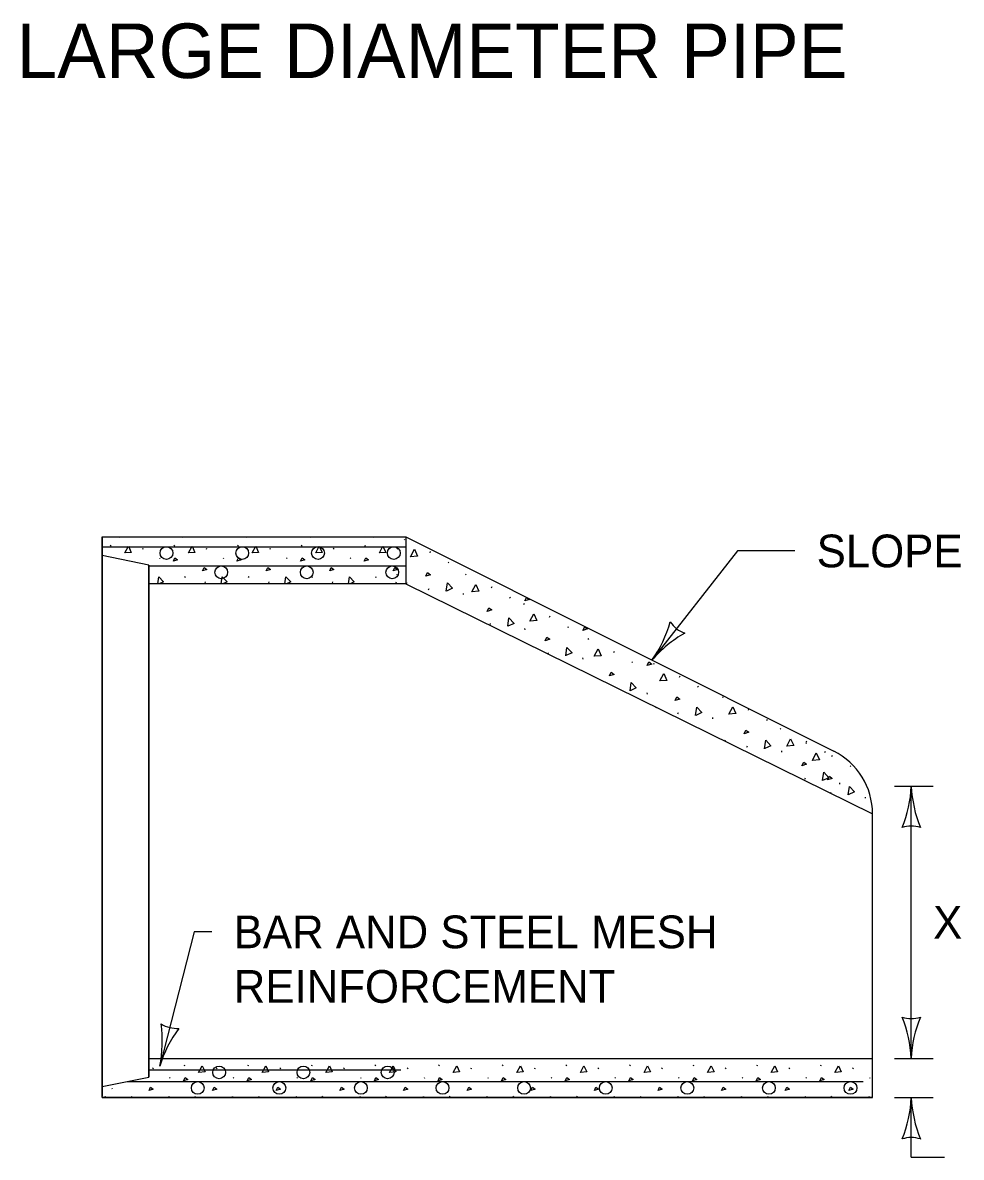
# Model space of a CAD drawing. Extents: x 49991.4 to 50021, y 49987.6 to 50011.4.
# Drawn here: x 50002.773 to 50004.494, y 49990.143 to 49992.222 of the extents above; entities that cross this region are included whole.
import ezdxf

# ---------------------------------------------------------------- set-up
doc = ezdxf.new("R2010")
doc.units = 0
for name, color, linetype in [('Level 1', 7, 'Continuous'), ('Level 2', 7, 'Continuous'), ('Level 3', 7, 'Continuous')]:
    doc.layers.add(name, color=color, linetype=linetype)

msp = doc.modelspace()

# ---------------------------------------------------------------- linework, layer by layer
at = {"layer": 'Level 1'}
for p, q in [((50002.9188, 49991.2797), (50003.4753, 49991.2797)), ((50002.9188, 49990.2549), (50002.9188, 49991.2797)), ((50002.9188, 49991.2797), (50002.9188, 49990.2723)), ((50002.9188, 49991.2797), (50003.4753, 49991.2797)), ((50002.9188, 49991.2797), (50002.9188, 49990.2549)), ((50002.9188, 49990.2549), (50002.9188, 49991.2797)), ((50002.9188, 49990.2549), (50002.9188, 49991.2797)), ((50002.9188, 49990.2549), (50002.9188, 49991.2797)), ((50002.9493, 49991.2797), (50002.9495, 49991.2793)), ((50002.9499, 49991.2797), (50002.9505, 49991.2788)), ((50003.0659, 49991.2797), (50003.0662, 49991.2793)), ((50003.0666, 49991.2797), (50003.0672, 49991.2788)), ((50003.1826, 49991.2797), (50003.1829, 49991.2793)), ((50003.1833, 49991.2797), (50003.1839, 49991.2788)), ((50003.2993, 49991.2797), (50003.2996, 49991.2793)), ((50003.3, 49991.2797), (50003.3006, 49991.2788)), ((50003.416, 49991.2797), (50003.4163, 49991.2793)), ((50003.4167, 49991.2797), (50003.4173, 49991.2788)), ((50003.4723, 49991.276), (50003.4734, 49991.2744)), ((50003.4753, 49991.2797), (50004.2605, 49990.8871)), ((50003.4753, 49991.2797), (50003.4753, 49991.1941)), ((50003.4753, 49991.2797), (50003.4753, 49991.1941)), ((50002.9342, 49991.2627), (50002.9352, 49991.2649)), ((50002.9931, 49991.2571), (50002.9941, 49991.2593)), ((50003.0509, 49991.2627), (50003.0518, 49991.2649)), ((50003.1098, 49991.2571), (50003.1108, 49991.2593)), ((50003.1676, 49991.2627), (50003.1685, 49991.2649)), ((50003.2265, 49991.2571), (50003.2275, 49991.2593)), ((50003.2843, 49991.2627), (50003.2852, 49991.2649)), ((50003.3432, 49991.2571), (50003.3442, 49991.2593)), ((50003.4009, 49991.2627), (50003.4019, 49991.2649)), ((50003.4599, 49991.2571), (50003.4609, 49991.2593)), ((50003.52, 49991.2507), (50003.5211, 49991.2531)), ((50003.0045, 49991.2283), (50002.9188, 49991.2455)), ((50003.0045, 49991.2283), (50002.9188, 49991.2455)), ((50002.9188, 49990.2523), (50002.9188, 49991.2455)), ((50003.0236, 49991.2416), (50003.0246, 49991.2401)), ((50003.1403, 49991.2416), (50003.1413, 49991.2401)), ((50003.257, 49991.2416), (50003.2579, 49991.2401)), ((50003.3737, 49991.2416), (50003.3746, 49991.2401)), ((50003.5533, 49991.2337), (50003.5544, 49991.2321)), ((50003.0045, 49990.2895), (50003.0045, 49991.2283)), ((50003.0045, 49991.2283), (50003.0045, 49990.2895)), ((50003.0045, 49991.2283), (50003.0045, 49990.2895)), ((50003.0045, 49991.2283), (50003.0045, 49990.2895)), ((50003.4582, 49991.2115), (50003.4589, 49991.2104)), ((50003.5849, 49991.2117), (50003.586, 49991.2101)), ((50003.4753, 49991.1941), (50003.0045, 49991.1941)), ((50003.4753, 49991.1941), (50003.0045, 49991.1941)), ((50003.0704, 49991.2053), (50003.0713, 49991.2074)), ((50003.1074, 49991.1953), (50003.1084, 49991.1975)), ((50003.1871, 49991.2053), (50003.188, 49991.2074)), ((50003.2241, 49991.1953), (50003.2251, 49991.1975)), ((50003.3037, 49991.2053), (50003.3047, 49991.2074)), ((50003.3408, 49991.1953), (50003.3417, 49991.1975)), ((50003.4204, 49991.2053), (50003.4214, 49991.2074)), ((50003.4575, 49991.1953), (50003.4584, 49991.1975)), ((50003.4753, 49991.1941), (50004.3315, 49990.7722)), ((50003.4769, 49991.194), (50003.4779, 49991.1964)), ((50003.6326, 49991.1864), (50003.6337, 49991.1888)), ((50003.5174, 49991.1831), (50003.5184, 49991.1855)), ((50003.5807, 49991.1764), (50003.581, 49991.174)), ((50003.6659, 49991.1694), (50003.667, 49991.1678)), ((50003.6914, 49991.1578), (50003.6925, 49991.1562)), ((50003.7391, 49991.1325), (50003.7402, 49991.1349)), ((50003.63, 49991.1188), (50003.631, 49991.1212)), ((50003.6933, 49991.1121), (50003.6936, 49991.1097)), ((50003.7724, 49991.1155), (50003.7735, 49991.1139)), ((50003.8092, 49991.0934), (50003.8103, 49991.0918)), ((50003.7365, 49991.0649), (50003.7375, 49991.0673)), ((50003.8569, 49991.0681), (50003.858, 49991.0705)), ((50003.7998, 49991.0582), (50003.8001, 49991.0558)), ((50003.8902, 49991.0511), (50003.8913, 49991.0495)), ((50003.9296, 49991.0483), (50003.9307, 49991.0467)), ((50003.9773, 49991.023), (50003.9784, 49991.0254)), ((50004.0106, 49991.006), (50004.0117, 49991.0044)), ((50003.9176, 49990.9938), (50003.9179, 49990.9914)), ((50004.0561, 49990.9874), (50004.0572, 49990.9858)), ((50003.9342, 49990.9663), (50003.9352, 49990.9687)), ((50004.1038, 49990.9621), (50004.1049, 49990.9645)), ((50003.9747, 49990.9554), (50003.9757, 49990.9578)), ((50004.038, 49990.9487), (50004.0383, 49990.9463)), ((50004.1371, 49990.9451), (50004.1382, 49990.9435)), ((50004.1623, 49990.9288), (50004.1634, 49990.9272)), ((50004.0607, 49990.9054), (50004.0617, 49990.9078)), ((50004.1012, 49990.8945), (50004.1022, 49990.8969)), ((50004.2094, 49990.9027), (50004.2105, 49990.9011)), ((50004.21, 49990.9035), (50004.2111, 49990.9059)), ((50004.1645, 49990.8878), (50004.1648, 49990.8854)), ((50004.2433, 49990.8865), (50004.2444, 49990.8849)), ((50004.2571, 49990.8774), (50004.2582, 49990.8798)), ((50004.2904, 49990.8604), (50004.2915, 49990.8588)), ((50004.2074, 49990.8359), (50004.2084, 49990.8383)), ((50004.2707, 49990.8292), (50004.271, 49990.8268)), ((50004.2545, 49990.8098), (50004.2555, 49990.8122)), ((50004.3178, 49990.8031), (50004.3181, 49990.8007)), ((50004.3315, 49990.2523), (50004.3315, 49990.7722)), ((50004.3315, 49990.2523), (50004.3315, 49990.7722)), ((50003.0045, 49990.3237), (50004.3315, 49990.3237)), ((50003.0045, 49990.2895), (50003.0045, 49990.3237)), ((50003.0045, 49990.3237), (50004.3315, 49990.3237)), ((50003.0118, 49990.3047), (50003.0128, 49990.3069)), ((50003.0696, 49990.3103), (50003.0705, 49990.3125)), ((50003.1285, 49990.3047), (50003.1295, 49990.3069)), ((50003.1862, 49990.3103), (50003.1872, 49990.3125)), ((50003.2452, 49990.3047), (50003.2462, 49990.3069)), ((50003.3029, 49990.3103), (50003.3039, 49990.3125)), ((50003.3619, 49990.3047), (50003.3629, 49990.3069)), ((50003.4196, 49990.3103), (50003.4206, 49990.3125)), ((50003.4786, 49990.3047), (50003.4796, 49990.3069)), ((50003.5363, 49990.3103), (50003.5373, 49990.3125)), ((50003.5953, 49990.3047), (50003.5962, 49990.3069)), ((50003.653, 49990.3103), (50003.654, 49990.3125)), ((50003.712, 49990.3047), (50003.7129, 49990.3069)), ((50003.7697, 49990.3103), (50003.7707, 49990.3125)), ((50003.8286, 49990.3047), (50003.8296, 49990.3069)), ((50003.8864, 49990.3103), (50003.8874, 49990.3125)), ((50003.9453, 49990.3047), (50003.9463, 49990.3069)), ((50004.0031, 49990.3103), (50004.004, 49990.3125)), ((50004.062, 49990.3047), (50004.063, 49990.3069)), ((50004.1198, 49990.3103), (50004.1207, 49990.3125)), ((50004.1787, 49990.3047), (50004.1797, 49990.3069)), ((50004.2365, 49990.3103), (50004.2374, 49990.3125)), ((50004.2954, 49990.3047), (50004.2964, 49990.3069)), ((50002.9188, 49990.2723), (50003.0045, 49990.2895)), ((50003.0423, 49990.2892), (50003.0432, 49990.2877)), ((50003.159, 49990.2892), (50003.1599, 49990.2877)), ((50003.2757, 49990.2892), (50003.2766, 49990.2877)), ((50003.3923, 49990.2892), (50003.3933, 49990.2877)), ((50003.509, 49990.2892), (50003.51, 49990.2877)), ((50003.6257, 49990.2892), (50003.6267, 49990.2877)), ((50003.7424, 49990.2892), (50003.7434, 49990.2877)), ((50003.8591, 49990.2892), (50003.8601, 49990.2877)), ((50003.9758, 49990.2892), (50003.9768, 49990.2877)), ((50004.0925, 49990.2892), (50004.0935, 49990.2877)), ((50004.2092, 49990.2892), (50004.2101, 49990.2877)), ((50004.3259, 49990.2892), (50004.3268, 49990.2877)), ((50004.3315, 49990.2523), (50002.9188, 49990.2523)), ((50004.3315, 49990.2523), (50002.9188, 49990.2523)), ((50002.9188, 49990.2523), (50004.3315, 49990.2523)), ((50002.9361, 49990.2696), (50002.9368, 49990.2685)), ((50002.9724, 49990.2529), (50002.9733, 49990.255)), ((50003.089, 49990.2529), (50003.09, 49990.255)), ((50003.2057, 49990.2529), (50003.2067, 49990.255)), ((50003.3224, 49990.2529), (50003.3234, 49990.255)), ((50003.4391, 49990.2529), (50003.4401, 49990.255)), ((50003.5558, 49990.2529), (50003.5568, 49990.255)), ((50003.6725, 49990.2529), (50003.6735, 49990.255)), ((50003.7892, 49990.2529), (50003.7902, 49990.255)), ((50003.9059, 49990.2529), (50003.9068, 49990.255)), ((50004.0226, 49990.2529), (50004.0235, 49990.255)), ((50004.1393, 49990.2529), (50004.1402, 49990.255)), ((50004.2559, 49990.2529), (50004.2569, 49990.255))]:
    msp.add_line(p, q, dxfattribs=at)
for points in [[(50002.9195, 49991.2619), (50003.4753, 49991.2619)], [(50002.9603, 49991.2506), (50002.9668, 49991.263), (50002.9719, 49991.2515), (50002.9605, 49991.2506)], [(50003.0769, 49991.2506), (50003.0835, 49991.263), (50003.0886, 49991.2515), (50003.0772, 49991.2506)], [(50003.1936, 49991.2506), (50003.2002, 49991.263), (50003.2053, 49991.2515), (50003.1939, 49991.2506)], [(50003.3103, 49991.2506), (50003.3169, 49991.263), (50003.322, 49991.2515), (50003.3106, 49991.2506)], [(50003.427, 49991.2506), (50003.4336, 49991.263), (50003.4387, 49991.2515), (50003.4273, 49991.2506)], [(50003.4841, 49991.2436), (50003.4913, 49991.2571), (50003.4969, 49991.2446), (50003.4843, 49991.2436)], [(50003.0492, 49991.2352), (50003.0521, 49991.2413), (50003.057, 49991.2377), (50003.0492, 49991.2352)], [(50003.1659, 49991.2352), (50003.1688, 49991.2413), (50003.1737, 49991.2377), (50003.1659, 49991.2352)], [(50003.2825, 49991.2352), (50003.2855, 49991.2413), (50003.2903, 49991.2377), (50003.2825, 49991.2352)], [(50003.3992, 49991.2352), (50003.4022, 49991.2413), (50003.407, 49991.2377), (50003.3992, 49991.2352)], [(50003.0048, 49991.2267), (50003.4753, 49991.2267)], [(50003.1026, 49991.2178), (50003.1055, 49991.2239), (50003.1104, 49991.2202), (50003.1026, 49991.2178)], [(50003.2193, 49991.2178), (50003.2222, 49991.2239), (50003.2271, 49991.2202), (50003.2193, 49991.2178)], [(50003.3359, 49991.2178), (50003.3389, 49991.2239), (50003.3437, 49991.2202), (50003.3359, 49991.2178)], [(50003.4526, 49991.2178), (50003.4556, 49991.2239), (50003.4604, 49991.2202), (50003.4526, 49991.2178)], [(50003.5121, 49991.2077), (50003.5153, 49991.2144), (50003.5206, 49991.2104), (50003.5121, 49991.2077)], [(50003.0205, 49991.1941), (50003.0223, 49991.2067), (50003.031, 49991.1977), (50003.0234, 49991.1941)], [(50003.1372, 49991.1941), (50003.139, 49991.2067), (50003.1477, 49991.1977), (50003.1401, 49991.1941)], [(50003.2539, 49991.1941), (50003.2556, 49991.2067), (50003.2644, 49991.1977), (50003.2567, 49991.1941)], [(50003.3706, 49991.1941), (50003.3723, 49991.2067), (50003.3811, 49991.1977), (50003.3734, 49991.1941)], [(50003.5498, 49991.1803), (50003.5519, 49991.1956), (50003.5614, 49991.1857), (50003.55, 49991.1804)], [(50003.5967, 49991.1793), (50003.6039, 49991.1928), (50003.6095, 49991.1803), (50003.5969, 49991.1793)], [(50003.6939, 49991.1625), (50003.6971, 49991.1691), (50003.7024, 49991.1651), (50003.6939, 49991.1625)], [(50003.6247, 49991.1434), (50003.6279, 49991.1501), (50003.6332, 49991.1461), (50003.6247, 49991.1434)], [(50003.6624, 49991.116), (50003.6645, 49991.1313), (50003.674, 49991.1214), (50003.6626, 49991.1161)], [(50003.7032, 49991.1254), (50003.7104, 49991.1389), (50003.716, 49991.1264), (50003.7034, 49991.1254)], [(50003.8004, 49991.1086), (50003.8036, 49991.1152), (50003.8089, 49991.1112), (50003.8004, 49991.1086)], [(50003.7312, 49991.0895), (50003.7344, 49991.0962), (50003.7397, 49991.0922), (50003.7312, 49991.0895)], [(50003.7689, 49991.0621), (50003.771, 49991.0774), (50003.7805, 49991.0675), (50003.7691, 49991.0622)], [(50003.821, 49991.061), (50003.8282, 49991.0745), (50003.8338, 49991.062), (50003.8212, 49991.061)], [(50003.9182, 49991.0442), (50003.9214, 49991.0508), (50003.9267, 49991.0468), (50003.9182, 49991.0442)], [(50003.849, 49991.0251), (50003.8522, 49991.0318), (50003.8575, 49991.0278), (50003.849, 49991.0251)], [(50003.9414, 49991.0159), (50003.9486, 49991.0294), (50003.9542, 49991.0169), (50003.9416, 49991.0159)], [(50003.8867, 49990.9977), (50003.8888, 49991.013), (50003.8983, 49991.0031), (50003.8869, 49990.9978)], [(50003.9694, 49990.98), (50003.9726, 49990.9867), (50003.9779, 49990.9827), (50003.9694, 49990.98)], [(50004.0071, 49990.9526), (50004.0092, 49990.9679), (50004.0187, 49990.958), (50004.0073, 49990.9527)], [(50004.0679, 49990.955), (50004.0751, 49990.9685), (50004.0807, 49990.956), (50004.0681, 49990.955)], [(50004.0959, 49990.9191), (50004.0991, 49990.9258), (50004.1044, 49990.9218), (50004.0959, 49990.9191)], [(50004.1336, 49990.8917), (50004.1357, 49990.907), (50004.1452, 49990.8971), (50004.1338, 49990.8918)], [(50004.1741, 49990.8964), (50004.1813, 49990.9099), (50004.1869, 49990.8974), (50004.1743, 49990.8964)], [(50004.2212, 49990.8703), (50004.2284, 49990.8838), (50004.234, 49990.8713), (50004.2214, 49990.8703)], [(50004.2021, 49990.8605), (50004.2053, 49990.8672), (50004.2106, 49990.8632), (50004.2021, 49990.8605)], [(50004.2398, 49990.8331), (50004.2419, 49990.8484), (50004.2514, 49990.8385), (50004.24, 49990.8332)], [(50004.2492, 49990.8344), (50004.2524, 49990.8411), (50004.2577, 49990.8371), (50004.2492, 49990.8344)], [(50004.2869, 49990.807), (50004.289, 49990.8223), (50004.2985, 49990.8124), (50004.2871, 49990.8071)], [(50003.0045, 49990.3031), (50003.4665, 49990.3031)], [(50003.0956, 49990.2982), (50003.1022, 49990.3106), (50003.1073, 49990.2991), (50003.0959, 49990.2982)], [(50003.2123, 49990.2982), (50003.2189, 49990.3106), (50003.224, 49990.2991), (50003.2126, 49990.2982)], [(50003.329, 49990.2982), (50003.3356, 49990.3106), (50003.3407, 49990.2991), (50003.3292, 49990.2982)], [(50003.4457, 49990.2982), (50003.4523, 49990.3106), (50003.4574, 49990.2991), (50003.4459, 49990.2982)], [(50003.5624, 49990.2982), (50003.569, 49990.3106), (50003.5741, 49990.2991), (50003.5626, 49990.2982)], [(50003.6791, 49990.2982), (50003.6857, 49990.3106), (50003.6908, 49990.2991), (50003.6793, 49990.2982)], [(50003.7958, 49990.2982), (50003.8023, 49990.3106), (50003.8075, 49990.2991), (50003.796, 49990.2982)], [(50003.9125, 49990.2982), (50003.919, 49990.3106), (50003.9241, 49990.2991), (50003.9127, 49990.2982)], [(50004.0291, 49990.2982), (50004.0357, 49990.3106), (50004.0408, 49990.2991), (50004.0294, 49990.2982)], [(50004.1458, 49990.2982), (50004.1524, 49990.3106), (50004.1575, 49990.2991), (50004.1461, 49990.2982)], [(50004.2625, 49990.2982), (50004.2691, 49990.3106), (50004.2742, 49990.2991), (50004.2628, 49990.2982)], [(50002.9651, 49990.2816), (50004.3146, 49990.2816)], [(50003.0679, 49990.2828), (50003.0708, 49990.2889), (50003.0756, 49990.2853), (50003.0679, 49990.2828)], [(50003.1845, 49990.2828), (50003.1875, 49990.2889), (50003.1923, 49990.2853), (50003.1845, 49990.2828)], [(50003.3012, 49990.2828), (50003.3042, 49990.2889), (50003.309, 49990.2853), (50003.3012, 49990.2828)], [(50003.4179, 49990.2828), (50003.4208, 49990.2889), (50003.4257, 49990.2853), (50003.4179, 49990.2828)], [(50003.5346, 49990.2828), (50003.5375, 49990.2889), (50003.5424, 49990.2853), (50003.5346, 49990.2828)], [(50003.6513, 49990.2828), (50003.6542, 49990.2889), (50003.6591, 49990.2853), (50003.6513, 49990.2828)], [(50003.768, 49990.2828), (50003.7709, 49990.2889), (50003.7758, 49990.2853), (50003.768, 49990.2828)], [(50003.8847, 49990.2828), (50003.8876, 49990.2889), (50003.8925, 49990.2853), (50003.8847, 49990.2828)], [(50004.0014, 49990.2828), (50004.0043, 49990.2889), (50004.0092, 49990.2853), (50004.0014, 49990.2828)], [(50004.1181, 49990.2828), (50004.121, 49990.2889), (50004.1259, 49990.2853), (50004.1181, 49990.2828)], [(50004.2347, 49990.2828), (50004.2377, 49990.2889), (50004.2425, 49990.2853), (50004.2347, 49990.2828)], [(50002.924, 49990.2523), (50002.9243, 49990.2543), (50002.9262, 49990.2523)], [(50003.0046, 49990.2654), (50003.0075, 49990.2715), (50003.0124, 49990.2678), (50003.0046, 49990.2654)], [(50003.0407, 49990.2523), (50003.041, 49990.2543), (50003.0429, 49990.2523)], [(50003.1213, 49990.2654), (50003.1242, 49990.2715), (50003.129, 49990.2678), (50003.1213, 49990.2654)], [(50003.1573, 49990.2523), (50003.1576, 49990.2543), (50003.1596, 49990.2523)], [(50003.2379, 49990.2654), (50003.2409, 49990.2715), (50003.2457, 49990.2678), (50003.2379, 49990.2654)], [(50003.274, 49990.2523), (50003.2743, 49990.2543), (50003.2763, 49990.2523)], [(50003.3546, 49990.2654), (50003.3576, 49990.2715), (50003.3624, 49990.2678), (50003.3546, 49990.2654)], [(50003.3907, 49990.2523), (50003.391, 49990.2543), (50003.3929, 49990.2523)], [(50003.4713, 49990.2654), (50003.4742, 49990.2715), (50003.4791, 49990.2678), (50003.4713, 49990.2654)], [(50003.5074, 49990.2523), (50003.5077, 49990.2543), (50003.5096, 49990.2523)], [(50003.588, 49990.2654), (50003.5909, 49990.2715), (50003.5958, 49990.2678), (50003.588, 49990.2654)], [(50003.6241, 49990.2523), (50003.6244, 49990.2543), (50003.6263, 49990.2523)], [(50003.7047, 49990.2654), (50003.7076, 49990.2715), (50003.7125, 49990.2678), (50003.7047, 49990.2654)], [(50003.7408, 49990.2523), (50003.7411, 49990.2543), (50003.743, 49990.2523)], [(50003.8214, 49990.2654), (50003.8243, 49990.2715), (50003.8292, 49990.2678), (50003.8214, 49990.2654)], [(50003.8575, 49990.2523), (50003.8578, 49990.2543), (50003.8597, 49990.2523)], [(50003.9381, 49990.2654), (50003.941, 49990.2715), (50003.9459, 49990.2678), (50003.9381, 49990.2654)], [(50003.9742, 49990.2523), (50003.9745, 49990.2543), (50003.9764, 49990.2523)], [(50004.0548, 49990.2654), (50004.0577, 49990.2715), (50004.0626, 49990.2678), (50004.0548, 49990.2654)], [(50004.0909, 49990.2523), (50004.0912, 49990.2543), (50004.0931, 49990.2523)], [(50004.1715, 49990.2654), (50004.1744, 49990.2715), (50004.1793, 49990.2678), (50004.1715, 49990.2654)], [(50004.2075, 49990.2523), (50004.2078, 49990.2543), (50004.2098, 49990.2523)], [(50004.2881, 49990.2654), (50004.2911, 49990.2715), (50004.2959, 49990.2678), (50004.2881, 49990.2654)], [(50004.3242, 49990.2523), (50004.3245, 49990.2543), (50004.3265, 49990.2523)]]:
    msp.add_lwpolyline(points, dxfattribs=at)
for centre in [(50003.0366, 49991.2502), (50003.1756, 49991.2502), (50003.3145, 49991.2502), (50003.4535, 49991.2502), (50003.1371, 49991.215), (50003.2939, 49991.215), (50003.4507, 49991.215), (50003.1332, 49990.2983), (50003.2877, 49990.2983), (50003.4422, 49990.2983), (50003.0939, 49990.2699), (50003.2436, 49990.2699), (50003.3932, 49990.2699), (50003.5429, 49990.2699), (50003.6925, 49990.2699), (50003.8422, 49990.2699), (50003.9918, 49990.2699), (50004.1415, 49990.2699), (50004.2911, 49990.2699)]:
    msp.add_circle(centre, 0.0117, dxfattribs=at)
msp.add_arc((50004.2031, 49990.7722), 0.1284, 0, 63.435, dxfattribs=at)
at = {"layer": 'Level 3'}
for p, q in [((50004.0838, 49991.2541), (50003.9269, 49991.0539)), ((50004.1891, 49991.2541), (50004.0838, 49991.2541)), ((50004.3715, 49990.8232), (50004.4425, 49990.8232)), ((50004.4025, 49990.3237), (50004.4025, 49990.8232)), ((50003.0873, 49990.5559), (50003.0243, 49990.3095)), ((50003.1199, 49990.5559), (50003.0873, 49990.5559)), ((50004.3715, 49990.3237), (50004.4425, 49990.3237)), ((50004.3715, 49990.2523), (50004.4425, 49990.2523)), ((50004.4025, 49990.1427), (50004.4025, 49990.2523)), ((50004.4025, 49990.1427), (50004.4632, 49990.1427))]:
    msp.add_line(p, q, dxfattribs=at)
for centre, radius, start, end in [((50003.7367, 49991.1884), 0.233, 324.7403, 343.9902), ((50004.006, 49991.1548), 0.0548, 214.0518, 249.7742), ((50004.0961, 49990.9097), 0.2223, 119.369, 139.5525), ((50004.1804, 49990.8324), 0.2223, 337.456, 357.6395), ((50004.6352, 49990.8347), 0.233, 182.8273, 202.0772), ((50004.4025, 49990.695), 0.0548, 72.1388, 107.8612), ((50004.4025, 49990.4519), 0.0548, 252.1388, 287.8612), ((50004.1698, 49990.3122), 0.233, 2.8273, 22.0772), ((50004.6246, 49990.3145), 0.2223, 157.456, 177.6395), ((50002.796, 49990.356), 0.233, 348.4851, 7.7349), ((50003.2372, 49990.2456), 0.2223, 143.1138, 163.2973), ((50003.0561, 49990.4337), 0.0548, 237.7966, 273.519), ((50004.1804, 49990.2615), 0.2223, 337.456, 357.6395), ((50004.6352, 49990.2638), 0.233, 182.8273, 202.0772), ((50004.4025, 49990.1241), 0.0548, 72.1388, 107.8612)]:
    msp.add_arc(centre, radius, start, end, dxfattribs=at)

# ---------------------------------------------------------------- texts
at = {"layer": 'Level 2'}
for s, height, p in [('LARGE DIAMETER PIPE', 0.1, (50002.7619, 49992.1209)), ('BAR AND STEEL MESH', 0.06, (50003.1599, 49990.5259)), ('X', 0.06, (50004.4425, 49990.5434)), ('REINFORCEMENT', 0.06, (50003.1599, 49990.4259))]:
    msp.add_text(s, height=height, dxfattribs=at).set_placement(p)
at = {"layer": 'Level 3'}
msp.add_text('SLOPE', height=0.06, dxfattribs=at).set_placement((50004.2291, 49991.2241))

doc.saveas('drawing.dxf')
